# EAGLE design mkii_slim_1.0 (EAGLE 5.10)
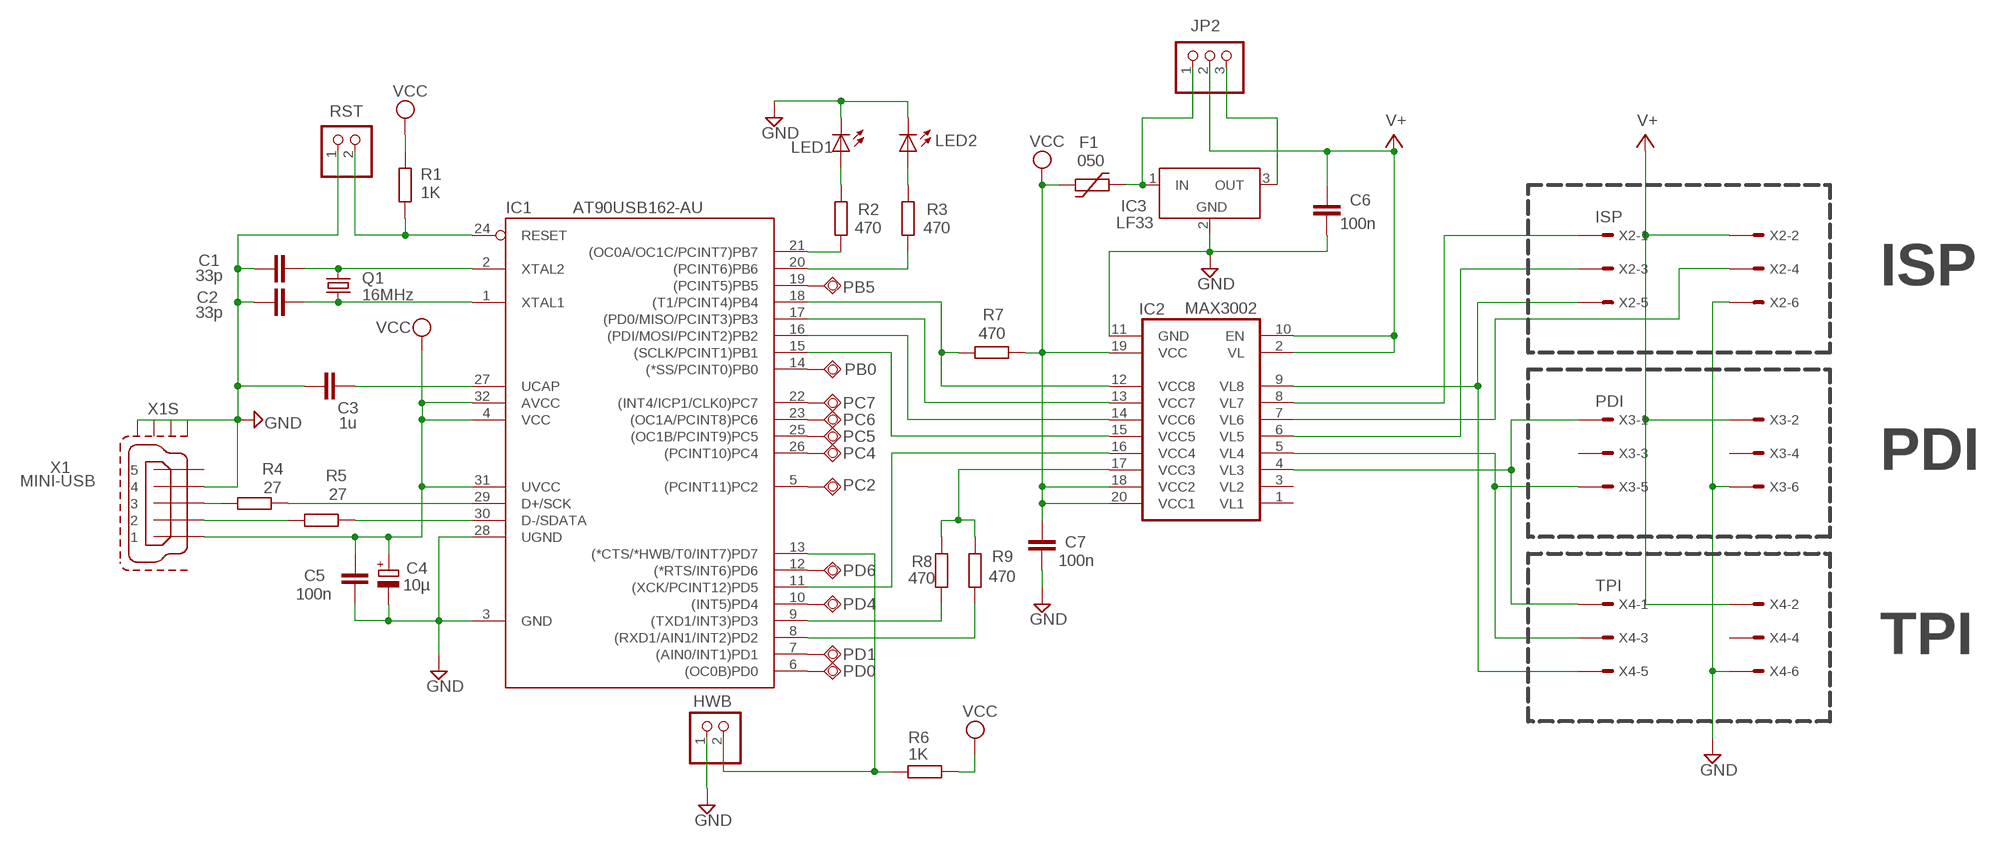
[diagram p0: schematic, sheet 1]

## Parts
C1  33p  C-EUC0805  [C0805]
C2  33p  C-EUC0805  [C0805]
C3  1u  C-EUC1206  [C1206]
C4  10µ  CPOL-EUC  [PANASONIC_C]
C5  100n  C-EUC0805  [C0805]
C6  100n  C-EUC0805  [C0805]
C7  100n  C-EUC0805  [C0805]
F1  050  1812L  [1812L]
HWB  PINHD-1X02_2.54-S  [1X02-S]
IC1  AT90USB162-AU  [TQFP32-08]
IC2  MAX3002  [TSSOP20]
IC3  LF33  LT1129CST5  [SOT223]
JP2  PINHD-1X03_2.54  [1X03]
LED1  LEDCHIPLED_0805  [CHIPLED_0805]
LED2  LEDCHIPLED_0805  [CHIPLED_0805]
PB0  TPSQB2,54  [B2,54]
PB5  TPSQB2,54  [B2,54]
PC2  TPSQB2,54  [B2,54]
PC4  TPSQB2,54  [B2,54]
PC5  TPSQB2,54  [B2,54]
PC6  TPSQB2,54  [B2,54]
PC7  TPSQB2,54  [B2,54]
PD0  TPSQB2,54  [B2,54]
PD1  TPSQB2,54  [B2,54]
PD4  TPSQB2,54  [B2,54]
PD6  TPSQB2,54  [B2,54]
Q1  16MHz  CRYSTALSM49  [SM49]
R1  1K  R-EU_M0805  [M0805]
R2  470  R-EU_M0805  [M0805]
R3  470  R-EU_M0805  [M0805]
R4  27  R-EU_M0805  [M0805]
R5  27  R-EU_M0805  [M0805]
R6  1K  R-EU_M0805  [M0805]
R7  470  R-EU_M0805  [M0805]
R8  470  R-EU_M0805  [M0805]
R9  470  R-EU_M0805  [M0805]
RST  PINHD-1X02_2.54-S  [1X02-S]
X1  MINI-USB  MINI-USB-SHIELD-UX60A-MB-5ST  [UX60A-MB-5ST]
X2  ISP  057-006-1  [057-006-1]
X3  PDI  057-006-1  [057-006-1]
X4  TPI  057-006-1  [057-006-1]

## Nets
GND: C1.1 C2.1 C3.1 C4.- C5.1 C6.1 C7.1 HWB.1 IC1.3(GND) IC1.28(UGND) IC2.11(GND) IC3.2(GND) LED1.C LED2.C RST.1 X1.4 X1.M1(S1) X1.M2(S2) X1.M3(S3) X1.M4(S4) X2.6 X3.6 X4.6
N$1: R4.2 X1.3
N$2: R5.2 X1.2
N$3: IC1.29(D+/SCK) R4.1
N$4: C3.2 IC1.27(UCAP)
N$5: C1.2 IC1.2(XTAL2) Q1.2
N$6: C2.2 IC1.1(XTAL1) Q1.1
N$7: IC1.30(D-/SDATA) R5.1
N$8: IC1.24(RESET) R1.1 RST.2
N$9: IC1.9((TXD1/INT3)PD3) R8.2
N$10: IC1.21((OC0A/OC1C/PCINT7)PB7) R2.2
N$11: IC1.20((PCINT6)PB6) R3.2
N$12: LED1.A R2.1
N$13: LED2.A R3.1
N$14: HWB.2 IC1.13((*CTS/*HWB/T0/INT7)PD7) R6.1
N$16: IC1.18((T1/PCINT4)PB4) IC2.12(VCC8) R7.2
N$17: IC1.17((PD0/MISO/PCINT3)PB3) IC2.13(VCC7)
N$18: IC1.16((PDI/MOSI/PCINT2)PB2) IC2.14(VCC6)
N$19: IC1.15((SCLK/PCINT1)PB1) IC2.15(VCC5)
N$20: IC1.11((XCK/PCINT12)PD5) IC2.16(VCC4)
N$21: IC2.17(VCC3) R8.1 R9.1
N$23: IC3.3(OUT) JP2.3
N$24: IC1.22((INT4/ICP1/CLK0)PC7) PC7.PP(TP)
N$25: IC2.4(VL3) X3.1 X4.1
N$26: IC2.5(VL4) X3.5 X4.3
N$27: IC2.9(VL8) X2.5 X4.5
N$28: IC2.8(VL7) X2.1
N$29: IC2.7(VL6) X2.4
N$30: IC2.6(VL5) X2.3
N$31: IC1.8((RXD1/AIN1/INT2)PD2) R9.2
N$32: F1.P$2 IC3.1(IN) JP2.1
N$33: IC1.23((OC1A/PCINT8)PC6) PC6.PP(TP)
N$34: IC1.25((OC1B/PCINT9)PC5) PC5.PP(TP)
N$35: IC1.14((*SS/PCINT0)PB0) PB0.PP(TP)
N$37: IC1.10((INT5)PD4) PD4.PP(TP)
N$38: IC1.7((AIN0/INT1)PD1) PD1.PP(TP)
N$39: IC1.6((OC0B)PD0) PD0.PP(TP)
N$40: IC1.5((PCINT11)PC2) PC2.PP(TP)
N$41: IC1.26((PCINT10)PC4) PC4.PP(TP)
N$42: IC1.12((*RTS/INT6)PD6) PD6.PP(TP)
N$54: IC1.19((PCINT5)PB5) PB5.PP(TP)
V+: C6.2 IC2.2(VL) IC2.10(EN) JP2.2 X2.2 X3.2 X4.2
VCC: C4.+ C5.2 C7.2 F1.P$1 IC1.4(VCC) IC1.31(UVCC) IC1.32(AVCC) IC2.18(VCC2) IC2.19(VCC) IC2.20(VCC1) R1.2 R6.2 R7.1 X1.1
Unconnected: IC2.1(VL1) IC2.3(VL2) X1.5 X3.3 X3.4 X4.4

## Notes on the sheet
- ISP
- PDI
- TPI

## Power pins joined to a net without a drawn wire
GND: IC3.4(GND)

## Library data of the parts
C1-C3 C5-C7 = rcl:C-EU: CAPACITOR, European symbol
C4 = rcl:CPOL-EU: POLARIZED CAPACITOR, European symbol
F1 = ptc-littlefuse:1812L
HWB RST = pinhead-2:PINHD-1X02: PIN HEADER
IC1 = at90usb:AT90USB162-*
IC2 = maxim-11:MAX30*: +1.2V to +5.5V, ±15kV ESD-Protected, 0.1?A, 35Mbps, 8-Channel Level Translators
IC3 = linear-technology:LT1129CST5: VOLTAGE REGULATOR with shutdown
JP2 = pinhead-2:PINHD-1X03: PIN HEADER
LED1 LED2 = led:LED: LED
PB0 PB5 PC2 PC4-PC7 PD0 PD1 PD4 PD6 = testpad:TPSQ: Test pad
Q1 = crystal:CRYSTAL: CRYSTAL
R1-R9 = rcl:R-EU_: RESISTOR, European symbol
X1 = con-hirose:MINI-USB-SHIELD-: MINI USB Connector Source: http://www.hirose.co.jp/cataloge_hp/e24000019.pdf
X2-X4 = con-panduit:057-006-: CONNECTOR 6-pin series 057 contact pc board low profile headers

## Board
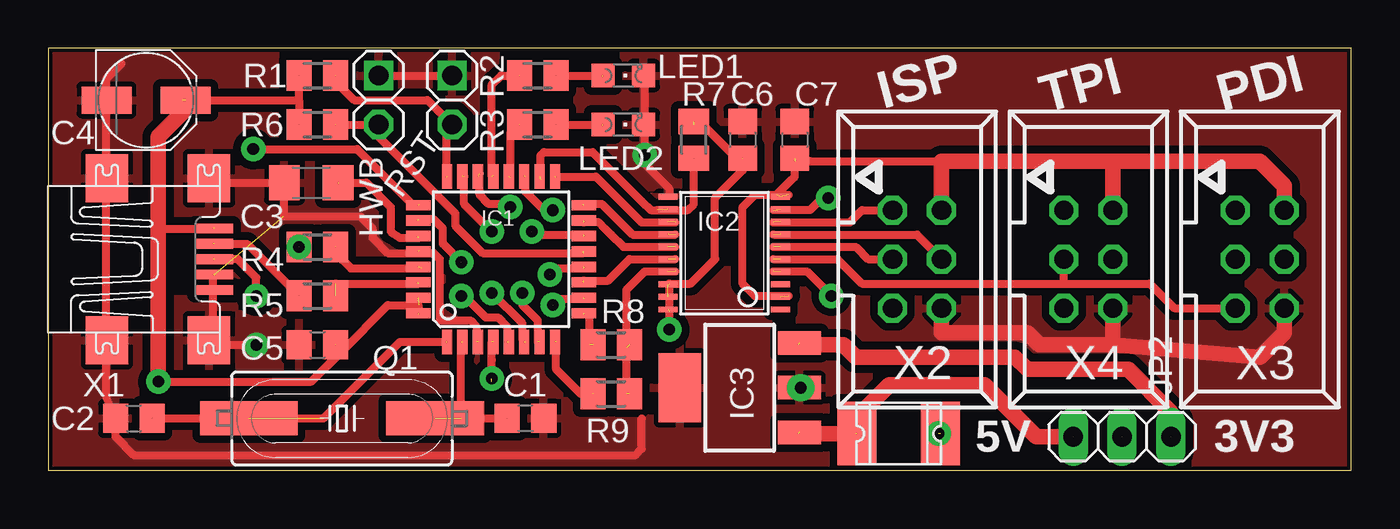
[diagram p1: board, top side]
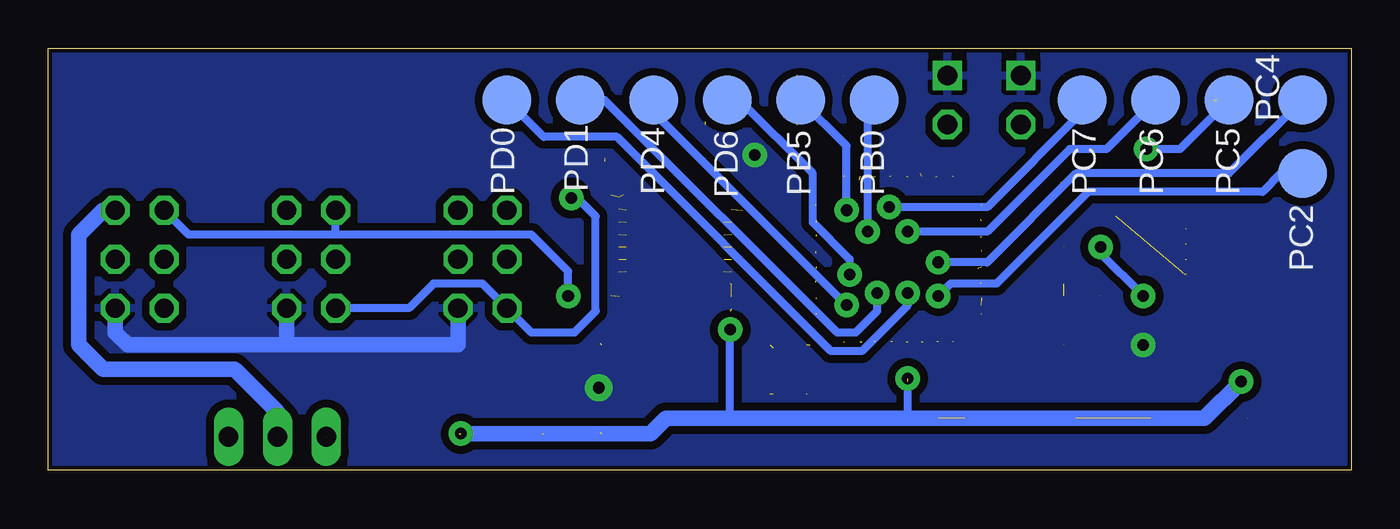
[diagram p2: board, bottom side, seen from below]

Size 67.61 x 21.9 mm. Coordinates in mm from the lower left corner, seen from the top.
Outline: 0,0 67.61,0 67.61,21.9 0,21.9 0,0
Copper layers (1*16): Top 0.035mm / dielectric 1.5mm / Bottom 0.035mm
Design rules "default *": minimum track width 10mil, minimum drill 24mil, track to track 16mil, track to pad 16mil, pad to pad 16mil, via to via 16mil, smd to smd 16mil, copper to edge 8mil, drill to drill 8mil, minimum pad ring 10mil, minimum via ring 8mil, stop-mask expansion 4mil, vias tented up to drill 32mil, thermal gap 10mil

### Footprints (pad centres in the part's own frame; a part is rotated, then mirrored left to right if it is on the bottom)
C0805 = smd 1.3 x 1.5: 1 -0.95,0; 2 0.95,0
C1206 = smd 1.6 x 1.8: 1 -1.4,0; 2 1.4,0
PANASONIC_C = smd 2.6 x 1.4: + 2.05,0; - -2.05,0
1812L = smd 2.03 x 3.3: P$1 -2.16,0; P$2 2.16,0
1X02-S = drill 1.016 square: 1 -1.27,0 | drill 1.016 octagon: 2 1.27,0
TQFP32-08 = smd 1.27 x 0.533: 1 -4.293,2.8; 2 -4.293,2; 3 -4.293,1.2; 4 -4.293,0.4; 5 -4.293,-0.4; 6 -4.293,-1.2; 7 -4.293,-2; 8 -4.293,-2.8; 17 4.293,-2.8; 18 4.293,-2; 19 4.293,-1.2; 20 4.293,-0.4; 21 4.293,0.4; 22 4.293,1.2; 23 4.293,2; 24 4.293,2.8 | smd 0.533 x 1.27: 9 -2.8,-4.293; 10 -2,-4.293; 11 -1.2,-4.293; 12 -0.4,-4.293; 13 0.4,-4.293; 14 1.2,-4.293; 15 2,-4.293; 16 2.8,-4.293; 25 2.8,4.293; 26 2,4.293; 27 1.2,4.293; 28 0.4,4.293; 29 -0.4,4.293; 30 -1.2,4.293; 31 -2,4.293; 32 -2.8,4.293
TSSOP20 = smd 0.305 x 0.991: 1 -2.925,-2.918; 2 -2.275,-2.918; 3 -1.625,-2.918; 4 -0.975,-2.918; 5 -0.325,-2.918; 6 0.325,-2.918; 7 0.975,-2.918; 8 1.625,-2.918; 9 2.275,-2.918; 10 2.925,-2.918; 11 2.925,2.918; 12 2.275,2.918; 13 1.625,2.918; 14 0.975,2.918; 15 0.325,2.918; 16 -0.325,2.918; 17 -0.975,2.918; 18 -1.625,2.918; 19 -2.275,2.918; 20 -2.925,2.918
SOT223 = smd 1.219 x 2.235: 1 -2.311,-3.099; 2 0,-3.099; 3 2.311,-3.099 | smd 3.6 x 2.2: 4 0,3.099
1X03 = drill 1.016 long: 1 -2.54,0; 2 0,0; 3 2.54,0
CHIPLED_0805 = smd 1.2 x 1.2: A 0,-1.05; C 0,1.05
B2,54 = smd 2.54 x 2.54: PP 0,0
SM49 = smd 5.08 x 1.778: 1 -4.826,0; 2 4.826,0
M0805 = smd 1.3 x 1.6: 1 -0.95,0; 2 0.95,0
UX60A-MB-5ST = smd 2 x 0.5: 1 2.25,1.6; 2 2.25,0.8; 3 2.25,0; 4 2.25,-0.8; 5 2.25,-1.6 | smd 2.2 x 2.5: M1 -3.3,-4.2; M2 -3.3,4.2; M3 2,4.2; M4 2,-4.2
057-006-1 = drill 1 octagon: 1 -2.54,-1.27; 2 -2.54,1.27; 3 0,-1.27; 4 0,1.27; 5 2.54,-1.27; 6 2.54,1.27

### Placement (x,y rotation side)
C1  24.77,2.7 180 top
C2  4.45,2.7 0 top
C3  13.65,14.92 0 top
C4  5.08,19.21 0 top
C5  13.97,6.51 0 top
C6  38.73,17.14 270 top
C7  36.04,17.15 270 top
F1  44.13,1.91 180 top
HWB  17.14,19.21 270 top
IC1  23.5,10.95 90 top
IC2  35.08,11.27 90 top
IC3  35.88,4.29 90 top
JP2  55.72,1.75 0 top
LED1  29.84,20.48 270 top
LED2  29.84,17.94 270 top
PB0  24.77,19.21 0 bottom
PB5  28.57,19.21 0 bottom
PC2  2.54,15.4 0 bottom
PC4  2.54,19.21 0 bottom
PC5  6.35,19.21 0 bottom
PC6  10.16,19.21 0 bottom
PC7  13.97,19.21 0 bottom
PD0  43.81,19.21 0 bottom
PD1  40.01,19.21 0 bottom
PD4  36.2,19.21 0 bottom
PD6  32.38,19.21 0 bottom
Q1  15.24,2.7 0 top
R1  13.97,20.48 180 top
R2  25.4,20.48 180 top
R3  25.4,17.94 180 top
R4  13.97,11.59 180 top
R5  13.97,9.05 180 top
R6  13.97,17.94 180 top
R7  33.5,17.15 270 top
R8  29.21,6.51 180 top
R9  29.21,3.97 180 top
RST  20.95,19.21 270 top
X1  6.35,10.95 0 top
X2  45.09,10.95 270 top
X3  62.87,10.95 270 top
X4  53.98,10.95 270 top

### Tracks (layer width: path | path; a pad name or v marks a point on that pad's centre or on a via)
GND  (via drill 0.6 pad 1.27, 0.6 pad 1.42)  (4 unrouted)
  Top 0.406: 19.21,11.27 19.21,11.43 | 19.21,11.27 17.62,11.27 16.83,12.07 16.83,12.54 16.19,13.18 12.22,13.18 12.22,14.92 8.41,14.92 | 19.21,11.27 20,11.27 20.32,10.95 20.32,7.78 21.91,7.78 22.23,7.46 22.23,6.67 | 30.8,2.7 30.8,1.11 30.48,0.79 4.45,0.79 3.49,1.75 C2.1 3.02,3.81 3.02,20.32 3.81,21.11 | 30.96,20.48 v30.96,16.35 30.96,15.88 32.23,14.61 32.23,14.29 | 8.57,10.16 8.57,6.51 v10.79,6.51 | HWB.1 RST.1
  Top 0.813: 55.24,6.51 51.44,6.51 50.8,7.14 46.35,7.14 X2.6 | 55.24,6.51 62.87,5.87 64.14,7.14 X3.6 | 55.24,6.51 X4.6
  Bottom 0.813: X2.6 46.35,6.51 55.24,6.51 | 55.24,6.51 63.5,6.51 64.14,7.14 X3.6 | 55.24,6.51 X4.6
  other vias: 39.05,4.29
  pour Top: 0,21.75 67.63,21.75 67.63,0.16 0,0.16
  pour Bottom: 0,21.75 0,0.16 67.63,0.16 67.63,21.75
N$1  (via drill 0.6 pad 1.27)  (2 unrouted)
  Top 0.406: 8.57,10.95 9.84,10.95 10.79,10 v10.79,9.05
  Bottom 0.406: R4.2 13.02,11.27 v10.79,9.05
  other vias: 13.02,11.59
N$2  (2 unrouted)
  Top 0.406: 8.57,11.75 10.32,11.75 R5.2 | R5.2
N$3  (2 unrouted)
  Top 0.406: R4.1 14.92,11.27 15.72,10.48 19.37,10.48
N$4  (2 unrouted)
  Top 0.406: 19.21,12.07 18.26,12.07 17.78,12.38 17.78,13.65 16.51,14.92 15.08,14.92
N$5  (3 unrouted)
  Top 0.406: 21.43,6.67 21.43,2.7 C1.2
N$6  (3 unrouted)
  Top 0.406: 20.64,6.67 18.26,6.67 14.29,2.7 C2.2
N$7  (2 unrouted)
  Top 0.406: 14.92,9.68 19.21,9.68
N$8  (2 unrouted)
  Top 0.406: 20.64,15.24 20.64,17.62 RST.2 19.68,19.21 15.88,19.21 14.92,20.16 R1.1
N$9  (2 unrouted)
  Top 0.406: 27.78,8.1 28.1,8.1 28.1,6.51
N$10  (2 unrouted)
  Top 0.406: 23.02,15.24 23.02,20 23.5,20.48 R2.2
N$11  (2 unrouted)
  Top 0.406: 23.81,15.24 23.97,15.24 23.97,17.46 R3.2
N$12  (2 unrouted)
  Top 0.406: R2.1 28.73,20.48
N$13  (2 unrouted)
  Top 0.406: R3.1 28.73,17.94
N$14  (2 unrouted)
  Top 0.406: 27.78,11.27 22.54,11.27 21.11,12.7 21.11,13.34 17.14,17.3 HWB.2 R6.1
N$16  (3 unrouted)
  Top 0.406: 25.56,15.08 25.56,16.35 25.72,16.51 28.26,16.51 30.8,13.97 31.27,13.49 31.59,13.49 33.18,13.49 33.5,13.81 R7.2
N$17  (2 unrouted)
  Top 0.406: 26.35,15.24 28.42,15.24 30.8,12.86 32.54,12.86
N$18  (2 unrouted)
  Top 0.406: 27.78,13.81 28.73,13.81 30.32,12.22 32.54,12.22
N$19  (2 unrouted)
  Top 0.406: 27.78,12.86 28.57,12.86 28.89,12.54 29.21,12.22 29.84,11.59 32.54,11.59
N$20  (2 unrouted)
  Top 0.406: 27.78,9.84 29.05,9.84 30.16,10.95 32.54,10.95
N$21  (3 unrouted)
  Top 0.406: 32.54,10.32 30.96,10.32 30,9.37 30,6.35 30,3.97
N$23  (2 unrouted)
  Top 0.813: JP2.3 58.26,3.02 56.04,5.24 50.8,5.24 50.16,5.87 41.91,5.87 41.27,6.51 38.89,6.51
N$24  (via drill 0.6 pad 1.27)  (1 unrouted)
  Top 0.406: v23.97,13.65 23.81,13.81 22.86,13.81 22.38,14.29 22.38,15.4
  Bottom 0.406: v23.97,13.65 18.89,13.65 13.97,18.57 PC7.PP
N$25  (via drill 0.6 pad 1.27)  (1 unrouted)
  Top 0.406: v40.64,9.05 39.37,10.32 37.62,10.32
  Bottom 0.406: 52.7,12.22 X4.1 | 52.7,12.22 42.55,12.22 40.64,10.32 v40.64,9.05 | 52.7,12.22 60.33,12.22 X3.1
N$26  (1 unrouted)
  Top 0.406: 37.62,10.95 40.96,10.95 42.23,9.68 52.7,9.68 | X3.5 58.42,8.41 57.15,9.68 52.7,9.68 | 52.7,9.68 X4.3
N$27  (via drill 0.6 pad 1.27)  (1 unrouted)
  Top 0.406: 37.62,13.49 39.53,13.49 40.16,14.13 v40.48,14.13
  Bottom 0.406: v40.48,14.13 40.16,14.13 39.21,13.18 39.21,8.26 40.32,7.14 42.55,7.14 X2.5 45.09,9.68 47.62,9.68 48.9,8.41 X4.5
N$28  (1 unrouted)
  Top 0.406: 37.62,12.86 41.59,12.86 42.23,13.49 X2.1
N$29  (1 unrouted)
  Top 0.406: X2.4 45.09,12.22 37.62,12.22
N$30  (1 unrouted)
  Top 0.406: X2.3 42.55,10.95 41.91,11.59 37.62,11.59
N$31  (2 unrouted)
  Top 0.406: 26.35,6.67 26.35,5.24 27.62,3.97 R9.2
N$32  (3 unrouted)
  Top 0.813: JP2.1 51.28,1.75 48.58,4.45 43.66,4.45 41.91,2.7 41.91,1.91 38.89,1.91
N$33  (via drill 0.6 pad 1.27)  (1 unrouted)
  Top 0.406: v23.02,12.38 21.59,13.81 21.59,15.24
  Bottom 0.406: v23.02,12.38 18.89,12.38 14.61,16.67 12.7,16.67 PC6.PP
N$34  (via drill 0.6 pad 1.27)  (1 unrouted)
  Top 0.406: v10.64,16.67 16.03,16.67 18.89,13.81 19.21,13.81
  Bottom 0.406: v10.64,16.67 8.89,16.67 PC5.PP
N$35  (via drill 0.6 pad 1.27)  (2 unrouted)
  Top 0.406: 27.78,12.22 25.24,12.22 v25.08,12.38
  Bottom 0.406: v25.08,12.38 25.08,18.89 PB0.PP
N$37  (2 unrouted)
  Top 0.406: 27.78,8.89 26.51,8.89 26.19,8.57
  Bottom 0.406: 26.19,8.57 36.2,18.57 PD4.PP
N$38  (via drill 0.6 pad 1.27)  (1 unrouted)
  Top 0.406: 25.4,6.67 25.4,7.78 24.61,8.57 v24.61,9.21
  Bottom 0.406: v24.61,9.21 24.61,8.26 25.72,7.14 26.67,7.14 38.73,19.21 PD1.PP
N$39  (via drill 0.6 pad 1.27)  (1 unrouted)
  Top 0.406: 24.77,6.67 24.61,6.83 24.61,7.62 v23.02,9.21
  Bottom 0.406: v23.02,9.21 23.02,8.57 25.4,6.19 26.99,6.19 38.1,17.3 41.91,17.3 PD0.PP
N$40  (via drill 0.6 pad 1.27)  (1 unrouted)
  Top 0.406: 23.81,6.67 23.81,7.46 23.34,7.94 22.7,7.94 21.59,9.05 v21.43,9.05
  Bottom 0.406: v21.43,9.05 20.8,9.68 18.41,9.68 13.65,14.45 4.6,14.45 3.65,15.4 PC2.PP
N$41  (via drill 0.6 pad 1.27)  (3 unrouted)
  Top 0.406: 19.21,13.02 20,13.02 20.48,12.54 20.48,11.75 v21.43,10.8
  Bottom 0.406: PC4.PP 6.35,15.4 14.29,15.4 18.89,10.8 v21.43,10.8
N$42  (via drill 0.6 pad 1.27)  (3 unrouted)
  Top 0.406: 27.78,10.64 27.78,10.48 26.35,10.48 v26.04,10.16
  Bottom 0.406: v26.04,10.16 26.04,10.95 27.94,12.86 27.94,15.4 31.75,19.21 PD6.PP
N$46  (via drill 0.6 pad 1.27)
  other vias: 26.19,8.57
N$54  (via drill 0.6 pad 1.27)  (1 unrouted)
  Top 0.406: 24.77,15.24 24.77,14.45 25.72,13.49 v26.19,13.49
  Bottom 0.406: v26.19,13.49 26.19,16.83 PB5.PP
V+  (5 unrouted)
  Top 0.406: 55.24,16.03 39.53,16.03 38.73,16.03 38.73,15.24 38.58,15.08 37.78,14.29 | 38.42,9.05 36.67,9.05 36.04,9.68 36.04,13.65 36.67,14.29 38.42,14.29
  Top 0.813: 55.24,16.03 62.87,16.03 64.14,14.76 X3.2 | 55.24,16.03 46.35,16.03 X2.2 | 55.24,16.03 X4.2
  Bottom 0.813: JP2.2 55.72,3.02 57.94,5.24 64.77,5.24 66.04,6.51 66.04,12.22 64.77,13.49 X3.2
VCC  (via drill 0.6 pad 1.27)  (15 unrouted)
  Top 0.406: 19.21,8.1 19.21,8.57 17.62,8.57 15.24,6.19 | v5.71,4.6 13.65,4.6 15.24,6.19 | 5.71,12.54 8.57,12.54 | 23.02,4.6 23.02,5.72 23.02,6.67 | 33.34,9.68 32.23,9.68 32.23,8.26 32.23,7.62 v32.23,7.3 | 33.34,9.68 | 33.34,9.68 34.61,10.95 34.61,14.13 36.04,15.56 C7.2 | 6.99,19.21 13.02,19.21 | 13.02,19.21 R1.2 | 13.02,19.21 R6.2 | 13.65,4.6 14.92,5.87 C5.2 15.24,6.19 | C7.2 35.72,16.19 33.97,17.94 33.5,17.94 | C7.2
  Top 0.813: v5.71,4.6 | v5.71,4.6 5.71,5.4 5.71,12.54 5.71,17.3 6.99,18.57 6.99,19.21
  Bottom 0.406: 23.02,2.7 v23.02,4.76 | 32.23,2.7 v32.23,7.3
  Bottom 0.813: v5.71,4.6 7.62,2.7 23.02,2.7 32.23,2.7 35.56,2.7 36.35,1.91 v46.2,1.91

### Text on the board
tNames: ISP | TPI | PDI | 5V | 3V3
bStop: DIY ELEKTRODA EU | USBTiny MKII SLIM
